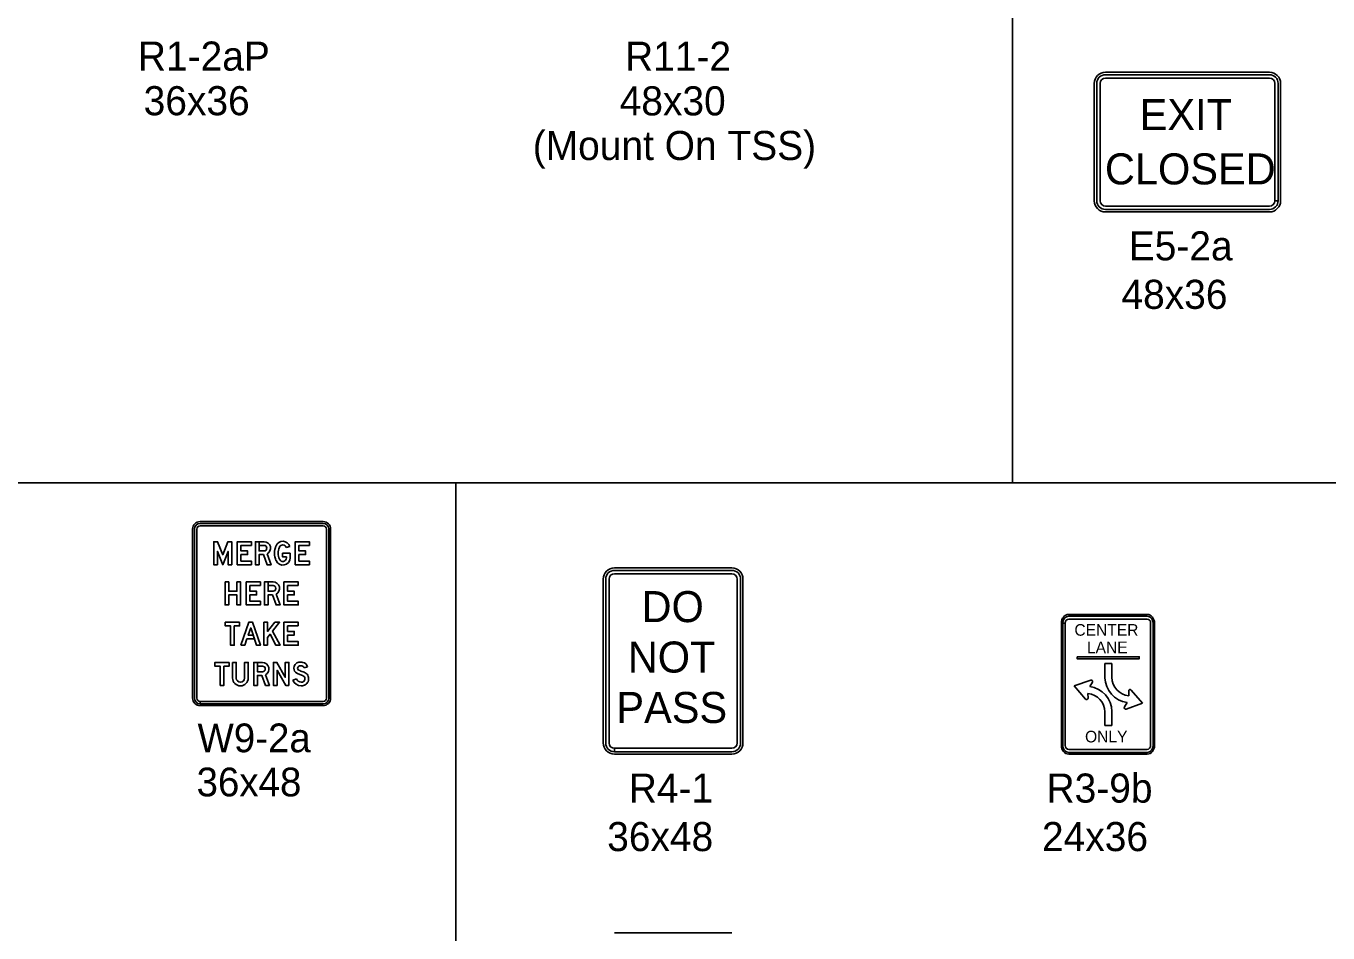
# Model space of a CAD drawing. Extents: x 1458 to 4498, y 17709 to 24109.
# Drawn here: x 3157 to 3828, y 20435 to 20903 of the extents above; entities that cross this region are included whole.
import ezdxf

# ---------------------------------------------------------------- set-up
doc = ezdxf.new("R2010")
doc.units = 0
doc.layers.add('P_ODOT_PLAN_TBlock', color=7, linetype='Continuous')
doc.layers.add('P_TRAF_TCP_General', color=7, linetype='Continuous')

msp = doc.modelspace()

# ---------------------------------------------------------------- linework, layer by layer
at = {"layer": 'P_ODOT_PLAN_TBlock'}
for p, q in [((3665.28, 21909.14), (3665.28, 20667.08)), ((1458.44, 20667.08), (3378.44, 20667.08)), ((3378.44, 20667.08), (3378.44, 19909.14)), ((3378.44, 20667.08), (4498.44, 20667.08))]:
    msp.add_line(p, q, dxfattribs=at)
at = {"layer": 'P_TRAF_TCP_General'}
for p, q in [((3797.61, 20878.76), (3713.14, 20878.76)), ((3707.39, 20873.01), (3707.39, 20812.53)), ((3708.64, 20873.01), (3708.64, 20812.53)), ((3708.64, 20873.01), (3708.64, 20812.53)), ((3710.39, 20812.53), (3710.39, 20873.01)), ((3797.61, 20877.51), (3713.14, 20877.51)), ((3797.61, 20877.51), (3713.14, 20877.51)), ((3713.14, 20875.76), (3797.61, 20875.76)), ((3800.36, 20873.01), (3800.36, 20812.55)), ((3802.11, 20812.53), (3802.11, 20873.01)), ((3802.11, 20812.55), (3802.11, 20873.01)), ((3803.35, 20812.54), (3803.35, 20873.01)), ((3800.36, 20812.55), (3802.11, 20812.55)), ((3802.11, 20812.53), (3800.36, 20812.53)), ((3797.61, 20809.79), (3713.14, 20809.79)), ((3713.14, 20808.04), (3797.61, 20808.04)), ((3713.14, 20808.04), (3797.61, 20808.04)), ((3713.14, 20806.79), (3797.61, 20806.79)), ((3310.12, 20647.19), (3246.76, 20647.19)), ((3310.12, 20646.26), (3246.76, 20646.26)), ((3246.76, 20645.03), (3310.12, 20645.03)), ((3242.87, 20643.3), (3242.87, 20556.23)), ((3243.79, 20643.3), (3243.79, 20556.23)), ((3245.03, 20556.23), (3245.03, 20643.3)), ((3311.85, 20643.3), (3311.85, 20556.23)), ((3313.08, 20556.23), (3313.08, 20643.3)), ((3314.01, 20556.23), (3314.01, 20643.3)), ((3291.15, 20633.81), (3292.96, 20634.38)), ((3520.67, 20623.3), (3460.2, 20623.3)), ((3454.45, 20617.55), (3454.45, 20533.09)), ((3455.7, 20617.55), (3455.7, 20533.09)), ((3457.45, 20533.09), (3457.45, 20617.55)), ((3520.67, 20622.05), (3460.2, 20622.05)), ((3460.2, 20620.3), (3520.67, 20620.3)), ((3523.42, 20617.55), (3523.42, 20533.09)), ((3525.17, 20533.09), (3525.17, 20617.55)), ((3526.42, 20533.09), (3526.42, 20617.55)), ((3734.68, 20599.31), (3694.2, 20599.31)), ((3734.68, 20598.41), (3694.2, 20598.41)), ((3734.68, 20598.41), (3694.2, 20598.41)), ((3694.2, 20596.91), (3734.68, 20596.91)), ((3690.45, 20594.81), (3690.45, 20531.84)), ((3691.2, 20594.81), (3691.2, 20531.84)), ((3691.2, 20594.81), (3692.45, 20594.81)), ((3691.2, 20594.8), (3691.2, 20531.84)), ((3692.45, 20594.8), (3691.2, 20594.8)), ((3692.45, 20531.84), (3692.45, 20594.8)), ((3736.43, 20594.81), (3736.43, 20531.84)), ((3737.68, 20531.84), (3737.68, 20594.81)), ((3737.68, 20531.84), (3737.68, 20594.81)), ((3738.43, 20531.84), (3738.43, 20594.81)), ((3263.5, 20574.57), (3263.5, 20566.54)), ((3712.83, 20566.73), (3712.83, 20574.02)), ((3712.83, 20574.02), (3716.44, 20574.02)), ((3716.44, 20574.02), (3716.44, 20566.97)), ((3696.99, 20562.54), (3705.55, 20565.51)), ((3706.4, 20564.45), (3705.01, 20562.15)), ((3702.91, 20555.69), (3696.99, 20562.54)), ((3704.14, 20558.62), (3704.19, 20556.18)), ((3704.14, 20558.62), (3704.14, 20558.62)), ((3725.16, 20557.46), (3725.1, 20559.9)), ((3725.16, 20557.46), (3725.16, 20557.46)), ((3726.38, 20560.39), (3732.31, 20553.54)), ((3246.76, 20553.26), (3246.76, 20554.5)), ((3246.76, 20552.34), (3310.12, 20552.34)), ((3310.12, 20554.5), (3246.77, 20554.5)), ((3246.77, 20554.5), (3246.77, 20553.26)), ((3246.77, 20553.26), (3310.12, 20553.26)), ((3722.89, 20551.63), (3724.28, 20553.93)), ((3732.31, 20553.54), (3723.74, 20550.57)), ((3712.86, 20542.06), (3712.86, 20549.11)), ((3716.46, 20549.35), (3716.46, 20542.06)), ((3716.46, 20542.06), (3712.86, 20542.06)), ((3460.2, 20528.59), (3460.2, 20530.34)), ((3520.67, 20530.34), (3460.22, 20530.34)), ((3460.22, 20530.34), (3460.22, 20528.59)), ((3734.68, 20529.74), (3694.2, 20529.74)), ((3460.2, 20527.34), (3520.67, 20527.34)), ((3460.22, 20528.59), (3520.67, 20528.59)), ((3694.2, 20528.24), (3734.68, 20528.24)), ((3694.2, 20528.24), (3734.68, 20528.24)), ((3694.2, 20527.34), (3734.68, 20527.34)), ((3520.72, 20435.17), (3460.17, 20435.17))]:
    msp.add_line(p, q, dxfattribs=at)
for points in [[(3263.02, 20624.96), (3263.02, 20636.82), (3261.06, 20636.82), (3258.4, 20630.11), (3255.74, 20636.82), (3253.78, 20636.82), (3253.78, 20624.96), (3255.67, 20624.96), (3255.67, 20631.84), (3258.4, 20624.96), (3261.13, 20631.84), (3261.13, 20624.96)], [(3273.22, 20634.92), (3267.77, 20634.92), (3267.77, 20632.07), (3271.21, 20632.07), (3271.21, 20630.18), (3267.77, 20630.18), (3267.77, 20626.86), (3273.22, 20626.86), (3273.22, 20624.96), (3265.87, 20624.96), (3265.87, 20636.82), (3273.22, 20636.82)], [(3303.1, 20634.92), (3297.65, 20634.92), (3297.65, 20632.07), (3301.09, 20632.07), (3301.09, 20630.18), (3297.65, 20630.18), (3297.65, 20626.86), (3303.1, 20626.86), (3303.1, 20624.96), (3295.75, 20624.96), (3295.75, 20636.82), (3303.1, 20636.82)], [(3259.59, 20616.07), (3261.48, 20616.07), (3261.48, 20611.32), (3265.75, 20611.32), (3265.75, 20616.07), (3267.65, 20616.07), (3267.65, 20604.21), (3265.75, 20604.21), (3265.75, 20609.43), (3261.48, 20609.43), (3261.48, 20604.21), (3259.59, 20604.21)], [(3277.85, 20614.17), (3272.39, 20614.17), (3272.39, 20611.32), (3275.84, 20611.32), (3275.84, 20609.43), (3272.39, 20609.43), (3272.39, 20606.11), (3277.85, 20606.11), (3277.85, 20604.21), (3270.49, 20604.21), (3270.49, 20616.07), (3277.85, 20616.07)], [(3297.29, 20614.17), (3291.84, 20614.17), (3291.84, 20611.32), (3295.28, 20611.32), (3295.28, 20609.43), (3291.84, 20609.43), (3291.84, 20606.11), (3297.29, 20606.11), (3297.29, 20604.21), (3289.94, 20604.21), (3289.94, 20616.07), (3297.29, 20616.07)], [(3267.06, 20595.32), (3267.06, 20593.42), (3264.33, 20593.42), (3264.33, 20583.46), (3262.43, 20583.46), (3262.43, 20593.42), (3259.7, 20593.42), (3259.7, 20595.32)], [(3267.77, 20583.46), (3271.8, 20595.32), (3273.81, 20595.32), (3277.85, 20583.46), (3275.84, 20583.46), (3272.81, 20592.39), (3271.52, 20588.62), (3274.09, 20588.62), (3274.73, 20586.72), (3270.88, 20586.72), (3269.77, 20583.46)], [(3281.52, 20583.46), (3281.52, 20587.48), (3282.8, 20589.11), (3285.78, 20583.46), (3287.92, 20583.46), (3284.09, 20590.75), (3287.68, 20595.32), (3285.27, 20595.32), (3281.52, 20590.55), (3281.52, 20595.32), (3279.62, 20595.32), (3279.62, 20583.46)], [(3297.29, 20593.42), (3291.84, 20593.42), (3291.84, 20590.58), (3295.28, 20590.58), (3295.28, 20588.68), (3291.84, 20588.68), (3291.84, 20585.36), (3297.29, 20585.36), (3297.29, 20583.46), (3289.94, 20583.46), (3289.94, 20595.32), (3297.29, 20595.32)], [(3698.52, 20577.52), (3730.51, 20577.52), (3730.51, 20576.52), (3698.52, 20576.52)], [(3261.72, 20574.57), (3261.72, 20572.67), (3258.99, 20572.67), (3258.99, 20562.71), (3257.1, 20562.71), (3257.1, 20572.67), (3254.37, 20572.67), (3254.37, 20574.57)], [(3292.55, 20562.71), (3292.55, 20574.57), (3290.65, 20574.57), (3290.65, 20566.95), (3286.3, 20574.57), (3284.49, 20574.57), (3284.49, 20562.71), (3286.38, 20562.71), (3286.38, 20570.6), (3290.89, 20562.71)]]:
    msp.add_lwpolyline(points, close=True, dxfattribs=at)
for points in [[(3279.74, 20632.07), (3277.13, 20632.07), (3277.13, 20636.82), (3275.24, 20636.82), (3275.24, 20624.96), (3277.13, 20624.96), (3277.13, 20630.18), (3279.36, 20630.18), (3281.28, 20624.96), (3283.3, 20624.96), (3281.25, 20630.54)], [(3277.13, 20636.82), (3277.13, 20634.92), (3279.74, 20634.92)], [(3279.74, 20636.82), (3277.13, 20636.82)], [(3279.74, 20634.92), (3277.13, 20634.92), (3277.13, 20632.07), (3279.74, 20632.07)], [(3289.23, 20630.89), (3289.23, 20628.99), (3291.24, 20628.99), (3291.24, 20628.55)], [(3293.14, 20628.55), (3293.14, 20630.89), (3289.23, 20630.89)], [(3284.36, 20611.32), (3281.76, 20611.32), (3281.76, 20616.07), (3279.86, 20616.07), (3279.86, 20604.21), (3281.76, 20604.21), (3281.76, 20609.43), (3283.98, 20609.43), (3285.9, 20604.21), (3287.92, 20604.21), (3285.87, 20609.79)], [(3281.76, 20616.07), (3281.76, 20614.17), (3284.36, 20614.17)], [(3284.36, 20616.07), (3281.76, 20616.07)], [(3265.4, 20566.54), (3265.4, 20574.57), (3263.5, 20574.57)], [(3271.56, 20566.54), (3271.56, 20574.57), (3269.67, 20574.57), (3269.67, 20566.54)], [(3278.91, 20569.83), (3276.3, 20569.83), (3276.3, 20574.57), (3274.41, 20574.57), (3274.41, 20562.71), (3276.3, 20562.71), (3276.3, 20567.93), (3278.53, 20567.93), (3280.45, 20562.71), (3282.47, 20562.71), (3280.42, 20568.29)], [(3276.31, 20574.57), (3276.31, 20572.67), (3278.91, 20572.67)], [(3278.91, 20574.57), (3276.31, 20574.57)], [(3300.31, 20571.78), (3302.11, 20572.38)], [(3296.34, 20566.16), (3294.56, 20565.49)]]:
    msp.add_lwpolyline(points, dxfattribs=at)
for centre, radius, start, end in [((3713.14, 20873.01), 5.75, 90, 180), ((3797.61, 20873.01), 5.75, 0, 90), ((3713.14, 20873.01), 4.5, 90, 180), ((3713.14, 20873.01), 4.5, 90, 180), ((3713.14, 20873.01), 2.75, 90, 180), ((3797.61, 20873.01), 4.5, 0, 90), ((3797.61, 20873.01), 4.5, 0, 90), ((3797.61, 20873.01), 2.75, 0, 90), ((3713.14, 20812.53), 5.75, 180, 270), ((3713.14, 20812.53), 4.5, 180, 270), ((3713.14, 20812.53), 4.5, 180, 270), ((3713.14, 20812.53), 2.75, 180, 270), ((3797.61, 20812.53), 4.5, 270, 0), ((3797.61, 20812.53), 4.5, 270, 0), ((3797.61, 20812.53), 2.75, 270, 0), ((3797.61, 20812.53), 5.75, 270, 0), ((3246.76, 20643.3), 3.89, 90, 180), ((3246.76, 20643.3), 2.96, 90, 180), ((3246.76, 20643.3), 1.73, 90, 180), ((3310.12, 20643.3), 3.89, 0, 90), ((3310.12, 20643.3), 2.96, 0, 90), ((3310.12, 20643.3), 1.73, 0, 90), ((3460.2, 20617.55), 5.75, 90, 180), ((3520.67, 20617.55), 5.75, 0, 90), ((3460.2, 20617.55), 4.5, 90, 180), ((3460.2, 20617.55), 2.75, 90, 180), ((3520.67, 20617.55), 4.5, 0, 90), ((3520.67, 20617.55), 2.75, 0, 90), ((3267.53, 20566.54), 4.03, 180, 0), ((3267.53, 20566.54), 2.13, 180, 0), ((3705.78, 20564.82), 0.725, 328.81539, 108.23911), ((3726.12, 20567.09), 13.29, 181.56827, 262.04727), ((3726.1, 20567.08), 9.67, 180.65654, 264.36875), ((3246.76, 20556.23), 3.89, 180, 270), ((3246.76, 20556.23), 2.96, 180, 270), ((3246.76, 20556.23), 1.73, 180, 270), ((3310.12, 20556.23), 2.96, 270, 0), ((3310.12, 20556.23), 1.73, 270, 0), ((3310.12, 20556.23), 3.89, 270, 0), ((3703.46, 20556.17), 0.725, 220.88851, 1.20762), ((3703.19, 20549), 9.67, 0.65654, 84.36875), ((3703.18, 20548.99), 13.29, 1.56827, 82.04727), ((3725.83, 20559.91), 0.725, 40.88851, 181.20762), ((3723.51, 20551.26), 0.725, 148.81539, 288.23911), ((3460.2, 20533.09), 5.75, 180, 270), ((3460.2, 20533.09), 4.5, 180, 270), ((3460.2, 20533.09), 2.75, 180, 270), ((3520.67, 20533.09), 4.5, 270, 0), ((3520.67, 20533.09), 2.75, 270, 0), ((3520.67, 20533.09), 5.75, 270, 0)]:
    msp.add_arc(centre, radius, start, end, dxfattribs=at)
for centre, major_axis, ratio, start_param, end_param in [((3279.74, 20633.5), (0, 3.32), 0.999993, 3.613317, 6.283185), ((3289.35, 20633.23), (0, 3.79), 0.999993, 5.021999, 7.454324), ((3279.74, 20633.5), (0, 1.42), 0.999993, 3.141593, 6.283185), ((3279.74, 20633.5), (0, 1.42), 0.999993, 3.141593, 6.283185), ((3294.89, 20630.89), (0, 9.81), 0.999993, 1.171139, 1.970454), ((3294.89, 20630.89), (0, 7.92), 0.999993, 1.171139, 1.970454), ((3289.35, 20633.23), (0, 1.9), 0.999993, 5.021999, 7.454324), ((3289.35, 20628.55), (0, 3.79), 0.999993, 1.970454, 4.712389), ((3289.35, 20628.55), (0, 1.9), 0.999993, 1.970454, 4.712389), ((3284.36, 20612.75), (0, 3.32), 0.999993, 3.613317, 6.283185), ((3284.36, 20612.75), (0, 1.42), 0.999993, 3.141593, 6.283185), ((3694.2, 20594.81), (0, -4.5), 0.833333, 3.141593, 4.712389), ((3694.2, 20594.81), (0, -3.6), 0.833333, 3.141593, 4.712389), ((3694.2, 20594.81), (0, -3.6), 0.833333, 3.141593, 4.712389), ((3694.2, 20594.81), (0, -2.1), 0.833333, 3.141593, 4.712389), ((3734.68, 20594.81), (0, -4.5), 0.833333, 1.570796, 3.141593), ((3734.68, 20594.81), (0, -3.6), 0.833333, 1.570796, 3.141593), ((3734.68, 20594.81), (0, -3.6), 0.833333, 1.570796, 3.141593), ((3734.68, 20594.81), (0, -2.1), 0.833333, 1.570796, 3.141593), ((3278.91, 20571.25), (0, 3.32), 0.999993, 3.613317, 6.283185), ((3278.91, 20571.25), (0, 1.42), 0.999993, 3.141593, 6.283185), ((3298.21, 20571.58), (0, 3.16), 0.999993, 0.175685, 1.570796), ((3297.98, 20571.58), (0, 2.92), 0.999993, 1.570796, 2.627164), ((3298.21, 20571.58), (0, 1.26), 0.999993, 0.175685, 1.570796), ((3297.98, 20571.58), (0, 1.03), 0.999993, 1.570796, 2.627164), ((3300.66, 20576.32), (0, 6.47), 0.999993, 2.627164, 2.834816), ((3298.56, 20569.63), (0, 5.14), 0.999993, 0.090794, 0.175685), ((3298.56, 20569.63), (0, 3.25), 0.999993, 0.090794, 0.175685), ((3298.72, 20567.88), (0, 6.9), 0.999993, 6.283185, 6.373979), ((3298.72, 20567.88), (0, 5), 0.999993, 0, 0.090794), ((3294.26, 20556.12), (0, 14.72), 0.999993, 5.820582, 5.976409), ((3298.72, 20571), (0, 3.77), 0.999993, 6.012094, 6.283185), ((3298.72, 20571), (0, 1.88), 0.999993, 6.012094, 6.283185), ((3298.79, 20571.27), (0, 1.6), 0.999993, 5.034126, 6.012094), ((3298.79, 20571.27), (0, 3.5), 0.999993, 5.034126, 6.012094), ((3298.88, 20567.12), (0, 4.61), 0.999993, 1.931277, 3.141593), ((3298.88, 20567.12), (0, 2.72), 0.999993, 1.931277, 3.141593), ((3300.66, 20576.32), (0, 8.37), 0.999993, 2.627164, 2.834816), ((3294.26, 20556.12), (0, 12.82), 0.999993, 5.820582, 5.976409), ((3298.88, 20566.62), (0, 2.22), 0.999993, 3.141593, 3.672524), ((3298.88, 20566.62), (0, 4.12), 0.999993, 3.141593, 3.672524), ((3299.42, 20566.46), (0, 1.26), 0.999993, 5.010707, 5.820582), ((3299.31, 20565.89), (0, 1.37), 0.999993, 3.672524, 4.331279), ((3298.71, 20566.13), (0, 2.02), 0.999993, 4.331279, 4.712389), ((3298.34, 20566.13), (0, 2.39), 0.999993, 4.712389, 5.010707), ((3299.42, 20566.46), (0, 3.16), 0.999993, 5.010707, 5.820582), ((3299.31, 20565.89), (0, 3.27), 0.999993, 3.672524, 4.331279), ((3298.71, 20566.13), (0, 3.92), 0.999993, 4.331279, 4.712389), ((3298.34, 20566.13), (0, 4.29), 0.999993, 4.712389, 5.010707), ((3694.2, 20531.84), (0, -4.5), 0.833333, 4.712389, 6.283185), ((3694.2, 20531.84), (0, -3.6), 0.833333, 4.712389, 6.283185), ((3694.2, 20531.84), (0, -3.6), 0.833333, 4.712389, 6.283185), ((3694.2, 20531.84), (0, -2.1), 0.833333, 4.712389, 6.283185), ((3734.68, 20531.84), (0, -3.6), 0.833333, 0, 1.570796), ((3734.68, 20531.84), (0, -3.6), 0.833333, 0, 1.570796), ((3734.68, 20531.84), (0, -2.1), 0.833333, 0, 1.570796), ((3734.68, 20531.84), (0, -4.5), 0.833333, 0, 1.570796)]:
    msp.add_ellipse(centre, major_axis=major_axis, ratio=ratio, start_param=start_param, end_param=end_param, dxfattribs=at)

# ---------------------------------------------------------------- texts
for s, height, p in [('R1-2aP', 14.994, (3214.71, 20879.59)), ('R11-2', 14.994, (3465.67, 20879.51)), ('36x36', 14.994, (3217.68, 20856.6)), ('48x30', 14.994, (3462.89, 20856.52)), ('EXIT', 15.994, (3730.77, 20848.94)), ('(Mount On TSS)', 14.994, (3418.12, 20833.52)), ('CLOSED', 15.994, (3712.86, 20820.96)), ('E5-2a', 14.994, (3725.14, 20781.8)), ('48x36', 14.994, (3721.37, 20756.81)), ('DO', 15.994, (3474.17, 20595.37)), ('CENTER', 5.998, (3697.15, 20588.36)), ('NOT', 15.994, (3467.07, 20569.38)), ('LANE', 5.998, (3703.6, 20579.37)), ('PASS', 15.994, (3461.2, 20543.39)), ('W9-2a', 14.822, (3245.42, 20528.3)), ('ONLY', 5.998, (3702.63, 20533.38)), ('36x48', 14.822, (3244.93, 20505.57)), ('R4-1', 14.994, (3467.59, 20502.35)), ('R3-9b', 14.994, (3682.78, 20502.35)), ('36x48', 14.994, (3456.46, 20477.36)), ('24x36', 14.994, (3680.44, 20477.36))]:
    msp.add_text(s, height=height, dxfattribs=at).set_placement(p)

doc.saveas('drawing.dxf')
